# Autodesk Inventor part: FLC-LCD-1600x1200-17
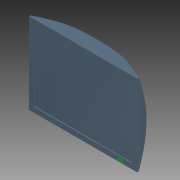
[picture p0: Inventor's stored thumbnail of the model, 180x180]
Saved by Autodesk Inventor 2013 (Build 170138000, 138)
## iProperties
Created: 2004-11
Part Number: FLC-LCD-1600x1200-17
Document SubType Name: Modeling
Designer: Autodesk, Inc.
Manufacturer: Standard
Standards Organization: Custom
Description: LCD MONITOR, 1600x1200, TOUCH
Mass: 4499.96 g
Surface Area: 2808.96 cm^2
Volume: 4499.96 cm^3
Density: 1 g/cm^3
Material: Allgemein
CAGE: 1LJX3
Dept. ID: Product Design
Description #2: ---
Finish #1: ---
Finish #2: ---
Material ID: ---
Project Number: ---
Author: Autodesk, Inc.
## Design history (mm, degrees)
sketch "Sketch1"
  geometry: L1 (-193.04, 144.78)-(193.04, 144.78); L2 (193.04, 144.78)-(193.04, -144.78); L3 (193.04, -144.78)-(-193.04, -144.78); L4 (-193.04, -144.78)-(-193.04, 144.78); L5 (-193.04, 144.78)-(193.04, -144.78); 3 further points
  constraints: 10 end point, 2 midpoint, 2 parallel, 1 horizontal, 1 horizontal alignment, 1 perpendicular, 1 vertical alignment
  dimensions: "d0" = 482.6 distance of L1.start L2.end; "d1" = 36.8699 deg angle of L3 L5
extrude "Extrusion1" new body sketch "Sketch1" stored distance "d2" = 50.8; taper "d3" = 0 deg
sketch "Sketch2"
  geometry: L1 (193.04, 144.78)-(193.04, -144.78) reference; L2 (-193.04, 144.78)-(193.04, 144.78) reference; L3 (-193.04, -144.78)-(-193.04, 144.78) reference; L4 (193.04, -144.78)-(-193.04, -144.78) reference; L5 (174.875, 126.615)-(174.875, -126.615); L6 (174.875, -126.615)-(-174.875, -126.615); L7 (-174.875, -126.615)-(-174.875, 126.615); L8 (-174.875, 126.615)-(174.875, 126.615); L9 (-174.875, 126.615)-(174.875, -126.615)
  constraints: 10 end point, 3 other
  dimensions: "d4" = 431.8 distance of L7.end L5.end
extrude "Extrusion2" cut sketch "Sketch2" distance "d5" = 3.175; taper "d6" = 0 deg
sketch "Sketch3"
  geometry: L1 (126.154, -132.337)-(139.952, -132.337); L2 (139.952, -132.337)-(139.952, -140.907); L3 (139.952, -140.907)-(126.154, -140.907); L4 (126.154, -140.907)-(126.154, -132.337); 2 further points
  constraints: 8 end point, 2 midpoint, 2 parallel, 2 vertical alignment, 1 horizontal, 1 perpendicular, 4 other
extrude "Extrusion3" join sketch "Sketch3" distance "d7" = 0.254; taper "d8" = 0 deg
sketch "Sketch4"
  geometry: L1 (193.04, -25.4)-(-193.04, -25.4) reference; L2 (193.04, 25.4)-(193.04, -25.4) reference; L3 (0, -57.634)-(0, 137.811) reference; L4 (0, -25.4)-(126.407, -25.4); A1 r 135.29 centre (126.407, 109.89) between (126.407, -25.4) and (193.04, -7.853)
  constraints: 3 point on line, 2 end point, 2 point on circle, 1 centre point, 1 midpoint, 1 tangent
revolve "Revolution1" sketch "Sketch4" stored, may be unused: angle "d10" = 90 deg
sketch "Sketch5"
  geometry: L1 (371.121, 0)-(0, 0) reference; L2 (66.633, -50.8)-(319.447, -50.8) reference; L3 (83.961, -50.8)-(287.161, -50.8); L4 (287.161, -50.8)-(287.161, -15.875); L5 (287.161, -15.875)-(83.961, -15.875); L6 (83.961, -15.875)-(83.961, -50.8); 2 further points
  constraints: 8 end point, 2 midpoint, 2 parallel, 1 horizontal, 1 perpendicular, 1 point on line, 1 vertical alignment
  dimensions: "d12" = 34.925 distance of L3.end L4.end; "d13" = 203.2 distance between parallel lines of L4 L6
extrude "Extrusion4" cut sketch "Sketch5" distance "d14" = 47.625; taper "d15" = 0 deg
sketch "Sketch6"
  geometry: 2 further points
  dimensions: "d16" = 50 horizontal distance of point (0, 0) point (-50, -50); "d17" = 50 horizontal distance of point (0, 0) point (-50, -50) (= d16)
hole "Hole1" sketch "Sketch6" diameter "d18" = 4.1402; stored, may be unused: countersink angle "d22" = 82 deg, drill point angle "d24" = 118 deg; dims "d19" = 12.7, "d20" = 9.525, "d21" = 6.35, "d23" = 12.7
pattern_linear "Rectangular Pattern1" dims "d27" = 100 (= 2 x d16)
sketch "Sketch9"
  geometry: L1 (83.961, -15.875)-(287.161, -15.875) reference; L2 (267.881, -41.95)-(249.291, -41.95); L3 (244.591, -37.25)-(244.591, -26.25); L4 (249.291, -21.55)-(267.881, -21.55); L5 (272.581, -26.25)-(272.581, -37.25); L6 (272.581, -31.75)-(244.591, -31.75); L7 (258.586, -41.95)-(258.586, -21.55); L8 (246.471, -37.25)-(246.471, -26.25); L9 (249.291, -23.43)-(267.881, -23.43); L10 (270.701, -26.25)-(270.701, -37.25); L11 (267.881, -40.07)-(249.291, -40.07); L12 (270.701, -28.535)-(265.596, -23.43); L13 (246.471, -28.535)-(251.576, -23.43); L14 (287.161, -15.875)-(287.161, -42.639) reference; A1 r 4.7 centre (267.881, -37.25) between (267.881, -41.95) and (272.581, -37.25); A2 r 4.7 centre (249.291, -37.25) between (244.591, -37.25) and (249.291, -41.95); A3 r 4.7 centre (249.291, -26.25) between (249.291, -21.55) and (244.591, -26.25); A4 r 4.7 centre (267.881, -26.25) between (272.581, -26.25) and (267.881, -21.55); A5 r 2.82 centre (249.291, -37.25) between (246.471, -37.25) and (249.291, -40.07); A6 r 2.82 centre (249.291, -26.25) between (249.291, -23.43) and (246.471, -26.25); A7 r 2.82 centre (267.881, -26.25) between (270.701, -26.25) and (267.881, -23.43); A8 r 2.82 centre (267.881, -37.25) between (267.881, -40.07) and (270.701, -37.25)
  constraints: 24 end point, 16 point on circle, 8 centre point, 8 tangent, 4 midpoint, 4 parallel, 4 point on line, 3 equal radius, 3 perpendicular, 1 horizontal, 8 other
  dimensions: "d74" = 4.7 radius of A1; "d75" = 20.4 distance between parallel lines of L4 L2; "d76" = 27.99 distance between parallel lines of L3 L5; "d77" = 24.23 distance between parallel lines of L8 L10; "d79" = 7.01 distance from line of L7 L12.end; "d80" = 28.575 distance between parallel lines of L14 L7; "d81" = 15.875 distance between parallel lines of L1 L6
extrude "Extrusion5" cut sketch "Sketch9" distance "d55" = 16.69; taper "d56" = 0 deg
extrude "Extrusion6" cut sketch "Sketch9" distance "d82" = 1.6002; taper "d83" = 0 deg
extrude "Extrusion7" join sketch "Sketch9" distance "d84" = 1; taper "d85" = 0 deg
sketch "Sketch10"
  geometry: L1 (258.586, -41.95)-(258.586, -21.55) reference; L2 (272.581, -31.75)-(244.591, -31.75) reference; L3 (258.086, -28.24)-(259.086, -28.24); L4 (259.086, -28.24)-(259.086, -31.24); L5 (259.086, -31.24)-(258.086, -31.24); L6 (258.086, -31.24)-(258.086, -28.24); L7 (251.076, -32.23)-(252.076, -32.23); L8 (252.076, -32.23)-(252.076, -35.23); L9 (252.076, -35.23)-(251.076, -35.23); L10 (251.076, -35.23)-(251.076, -32.23); L11 (265.096, -32.23)-(266.096, -32.23); L12 (266.096, -32.23)-(266.096, -35.23); L13 (266.096, -35.23)-(265.096, -35.23); L14 (265.096, -35.23)-(265.096, -32.23); 3 further points
  constraints: 24 end point, 6 parallel, 3 equal length, 3 horizontal, 3 midpoint, 3 perpendicular, 4 other
  dimensions: "d86" = 1 distance of L3.start L3.end; "d87" = 3 distance of L5.end L3.start; "d88" = 2.01 distance from line of L2 point (259.086, -29.74); "d89" = 1.98 distance from line of L2 point (266.096, -33.73); "d90" = 7.01 distance from line of L1 point (265.596, -32.23)
extrude "Extrusion8" join sketch "Sketch10" distance "d91" = 9.525; taper "d92" = 0 deg
sketch "Sketch14"
  geometry: L1 (134.076, -30.75)-(134.076, -34.34); L2 (132.806, -35.61)-(111.316, -35.61); L3 (110.046, -34.34)-(110.046, -30.75); L4 (110.046, -30.75)-(110.449, -29.246); L5 (112.216, -27.89)-(131.905, -27.89); L6 (133.673, -29.246)-(134.076, -30.75); L7 (122.061, -35.61)-(122.061, -27.89); L8 (83.961, -15.875)-(287.161, -15.875) reference; L9 (83.961, -39.176)-(83.961, -15.875) reference; L10 (111.316, -35)-(132.806, -35); L11 (133.466, -34.34)-(133.466, -30.83); L12 (133.466, -30.83)-(133.084, -29.404); L13 (131.905, -28.5)-(112.216, -28.5); L14 (111.038, -29.404)-(110.656, -30.83); L15 (110.656, -30.83)-(110.656, -34.34); L16 (134.076, -31.75)-(110.046, -31.75); L17 (132.361, -30.59)-(130.861, -30.59); L18 (130.861, -30.59)-(130.861, -29.09); L19 (130.861, -29.09)-(132.361, -29.09); L20 (132.361, -29.09)-(132.361, -30.59); L21 (130.451, -30.59)-(128.951, -30.59); L22 (128.951, -30.59)-(128.951, -29.09); L23 (128.951, -29.09)-(130.451, -29.09); L24 (130.451, -29.09)-(130.451, -30.59); L25 (128.541, -30.59)-(127.041, -30.59); L26 (127.041, -30.59)-(127.041, -29.09); L27 (127.041, -29.09)-(128.541, -29.09); L28 (128.541, -29.09)-(128.541, -30.59); L29 (126.631, -30.59)-(125.131, -30.59); L30 (125.131, -30.59)-(125.131, -29.09); L31 (125.131, -29.09)-(126.631, -29.09); L32 (126.631, -29.09)-(126.631, -30.59); L33 (124.721, -30.59)-(123.221, -30.59); L34 (123.221, -30.59)-(123.221, -29.09); L35 (123.221, -29.09)-(124.721, -29.09); L36 (124.721, -29.09)-(124.721, -30.59); L37 (122.811, -30.59)-(121.311, -30.59); L38 (121.311, -30.59)-(121.311, -29.09); L39 (121.311, -29.09)-(122.811, -29.09); L40 (122.811, -29.09)-(122.811, -30.59); L41 (120.901, -30.59)-(119.401, -30.59); L42 (119.401, -30.59)-(119.401, -29.09); L43 (119.401, -29.09)-(120.901, -29.09); L44 (120.901, -29.09)-(120.901, -30.59); L45 (118.991, -30.59)-(117.491, -30.59); L46 (117.491, -30.59)-(117.491, -29.09); L47 (117.491, -29.09)-(118.991, -29.09); L48 (118.991, -29.09)-(118.991, -30.59); L49 (132.361, -32.5)-(130.861, -32.5); L50 (130.861, -32.5)-(130.861, -31); L51 (130.861, -31)-(132.361, -31); L52 (132.361, -31)-(132.361, -32.5); L53 (130.451, -32.5)-(128.951, -32.5); L54 (128.951, -32.5)-(128.951, -31); L55 (128.951, -31)-(130.451, -31); L56 (130.451, -31)-(130.451, -32.5); L57 (128.541, -32.5)-(127.041, -32.5); L58 (127.041, -32.5)-(127.041, -31); L59 (127.041, -31)-(128.541, -31); L60 (128.541, -31)-(128.541, -32.5); L61 (126.631, -32.5)-(125.131, -32.5); L62 (125.131, -32.5)-(125.131, -31); L63 (125.131, -31)-(126.631, -31); L64 (126.631, -31)-(126.631, -32.5)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; A1 r 1.27 centre (132.806, -34.34) between (132.806, -35.61) and (134.076, -34.34); A2 r 1.27 centre (111.316, -34.34) between (110.046, -34.34) and (111.316, -35.61); A3 r 1.83 centre (112.216, -29.72) between (112.216, -27.89) and (110.449, -29.246); A4 r 1.83 centre (131.905, -29.72) between (133.673, -29.246) and (131.905, -27.89); A5 r 0.66 centre (132.806, -34.34) between (132.806, -35) and (133.466, -34.34); A6 r 1.22 centre (131.905, -29.72) between (133.084, -29.404) and (131.905, -28.5); A7 r 1.22 centre (112.216, -29.72) between (112.216, -28.5) and (111.038, -29.404); A8 r 0.66 centre (111.316, -34.34) between (110.656, -34.34) and (111.316, -35); 7 further points
  constraints: 270 end point, 16 point on circle, 13 symmetric about line, 12 parallel, 12 perpendicular, 10 midpoint, 8 centre point, 8 tangent, 5 horizontal, 4 point on line, 2 vertical, 1 horizontal alignment, 1 vertical alignment, 197 other
  dimensions: "d100" = 24.03 distance between parallel lines of L3 L1; "d101" = 1.27 radius of A2; "d102" = 1.83 radius of A3; "d103" = 105 deg angle of L6 L5; "d104" = 7.72 distance between parallel lines of L5 L2; "d105" = 3.59 distance of L3.start L3.end; "d106" = 15.875 distance from line of L8 point (122.061, -31.75); "d107" = 38.1 distance between parallel lines of L9 L7; "d108" = 6.5 distance between parallel lines of L13 L10; "d110" = 1.5 distance of L18.end L19.end; "d111" = 10.3 distance between parallel lines of L7 L20; "d112" = 2.66 distance between parallel lines of L16 L19; "d115" = 1.91 distance of L17.start L21.start; "d118" = 1.91 distance of L17.start L49.start; "d121" = 0.5 distance of L119.end L117.start; "d122" = 0.25 distance between parallel lines of L16 L119 (= 0.5 x d121); "d123" = 4.2 distance of L113.end L114.end; "d124" = 8.69 distance between parallel lines of L116 L7; "d125" = 1.25 distance of L122.end L123.end; "d126" = 0.4 distance between parallel lines of L116 L122; "d127" = 0.4 distance between parallel lines of L119 L121; "d134" = 32.51 distance of point (138.316, -31.75) point (105.806, -31.75)
extrude "Extrusion9" cut sketch "Sketch14" distance "d128" = 6.5; taper "d129" = 0 deg
extrude "Extrusion10" cut sketch "Sketch14" distance "d130" = 7.5; taper "d131" = 0 deg
extrude "Extrusion11" join sketch "Sketch14" distance "d132" = 0.25; taper "d133" = 0 deg
hole "Hole3" sketch "Sketch14" diameter "d135" = 2.159; stored, may be unused: countersink angle "d139" = 82 deg, drill point angle "d141" = 118 deg; dims "d136" = 12.7, "d137" = 9.525, "d138" = 6.35, "d140" = 9.525
sketch "Sketch15"
  geometry: L1 (168.353, -32.872)-(167.806, -29.773); L2 (165.38, -27.737)-(154.941, -27.737); L3 (152.515, -29.773)-(151.968, -32.872); L4 (154.395, -35.763)-(165.926, -35.763); L5 (160.161, -35.763)-(160.161, -27.737); L6 (83.961, -15.875)-(287.161, -15.875) reference; L7 (83.961, -39.176)-(83.961, -15.875) reference; L8 (165.926, -35.509)-(154.395, -35.509); L9 (152.219, -32.916)-(152.765, -29.817); L10 (154.941, -27.991)-(165.38, -27.991); L11 (167.556, -29.817)-(168.103, -32.916); L12 (168.155, -31.75)-(152.166, -31.75); L13 (165.647, -33.172)-(164.275, -30.328); C1 r 0.635 at (165.647, -33.172); C2 r 0.635 at (162.904, -33.172); C3 r 0.635 at (160.161, -33.172); C4 r 0.635 at (157.417, -33.172); C5 r 0.635 at (154.674, -33.172); C6 r 0.635 at (164.275, -30.328); C7 r 0.635 at (161.532, -30.328); C8 r 0.635 at (158.789, -30.328); C9 r 0.635 at (156.046, -30.328); C10 r 0.635 at (153.303, -30.328); C11 r 1.905 at (147.727, -31.75); C12 r 1.905 at (172.594, -31.75); A1 r 2.464 centre (165.38, -30.201) between (167.806, -29.773) and (165.38, -27.737); A2 r 2.464 centre (154.941, -30.201) between (154.941, -27.737) and (152.515, -29.773); A3 r 2.464 centre (154.395, -33.299) between (151.968, -32.872) and (154.395, -35.763); A4 r 2.464 centre (165.926, -33.299) between (165.926, -35.763) and (168.353, -32.872); A5 r 2.21 centre (154.395, -33.299) between (152.219, -32.916) and (154.395, -35.509); A6 r 2.21 centre (154.941, -30.201) between (154.941, -27.991) and (152.765, -29.817); A7 r 2.21 centre (165.38, -30.201) between (167.556, -29.817) and (165.38, -27.991); A8 r 2.21 centre (165.926, -33.299) between (165.926, -35.509) and (168.103, -32.916); 1 further point
  constraints: 22 end point, 20 centre point, 16 point on circle, 7 tangent, 4 midpoint, 4 point on line, 3 parallel, 2 horizontal, 1 equal radius, 1 perpendicular, 30 other
  dimensions: "d142" = 16.4592 dimension on A3 A4; "d143" = 2.4638 radius of A3; "d144" = 10 deg angle of L5 L1; "d145" = 8.0264 distance between parallel lines of L2 L4; "d147" = 76.2 distance between parallel lines of L7 L5; "d148" = 0.254 distance between parallel lines of L4 L8; "d149" = 15.875 distance between parallel lines of L6 L12; "d150" = 1.27 diameter of C1; "d151" = 1.4224 distance from line of L12 L13.start; "d152" = 5.4864 distance from line of L13.start L5; "d153" = 1.4224 distance from line of L13.end L12 (= d151); "d154" = 4.1148 distance from line of L13.end L5; "d155" = 3.15819 distance of L13.start L13.end (derived); "d158" = 2.7432 distance of L13.start C2.centre; "d161" = 3.15819 distance of L13.start C6.centre (= d155); "d166" = 3.81 diameter of C11; "d174" = 24.8666 distance of C12.centre C11.centre
extrude "Extrusion12" join sketch "Sketch15" distance "d164" = 6.0452; taper "d165" = 0 deg
sketch "Sketch16"
  geometry: C1 r 1.905 at (0, 0) reference; C2 r 1.905 at (24.867, 0) reference
hole "Hole4" sketch "Sketch16" diameter "d167" = 2.159; stored, may be unused: countersink angle "d171" = 82 deg, drill point angle "d173" = 118 deg; dims "d168" = 12.7, "d169" = 9.525, "d170" = 6.35, "d172" = 6.35
sketch "Sketch17"
  geometry: L1 (202.486, -27.86)-(202.486, -34.01); L2 (202.486, -34.01)-(200.856, -35.64); L3 (200.856, -35.64)-(195.666, -35.64); L4 (195.666, -35.64)-(194.036, -34.01); L5 (194.036, -34.01)-(194.036, -27.86); L6 (194.036, -27.86)-(202.486, -27.86); L7 (198.261, -35.64)-(198.261, -27.86); L8 (83.961, -15.875)-(287.161, -15.875) reference; L9 (83.961, -39.176)-(83.961, -15.875) reference; L10 (201.061, -33.34)-(195.461, -33.34); L11 (195.461, -33.34)-(195.461, -30.16); L12 (195.461, -30.16)-(201.061, -30.16); L13 (201.061, -30.16)-(201.061, -33.34); 3 further points
  constraints: 22 end point, 5 midpoint, 4 parallel, 4 perpendicular, 1 horizontal, 1 horizontal alignment, 1 vertical, 1 vertical alignment, 1 other
  dimensions: "d175" = 8.45 distance between parallel lines of L5 L1; "d176" = 7.78 distance between parallel lines of L6 L3; "d177" = 1.63 horizontal distance of L3.end L4.end; "d178" = 15.875 distance from line of point (198.261, -31.75) L8; "d179" = 114.3 distance between parallel lines of L9 L7; "d180" = 3.18 distance of L12.end L10.start; "d181" = 5.6 distance of L10.start L10.end
extrude "USB BPort" cut sketch "Sketch17" distance "d182" = 6.35; taper "d183" = 0 deg
sketch "Sketch18"
  geometry: L1 (-168.818, 126.615)-(168.818, 126.615); L2 (168.818, 126.615)-(168.818, -126.615); L3 (168.818, -126.615)-(-168.818, -126.615); L4 (-168.818, -126.615)-(-168.818, 126.615); L5 (174.875, 126.615)-(-174.875, 126.615) reference; L6 (-174.875, 126.615)-(-174.875, -126.615) reference; L7 (-174.875, -126.615)-(174.875, -126.615) reference; L8 (174.875, -126.615)-(174.875, 126.615) reference; L9 (-174.875, 126.615)-(174.875, 126.615) reference; L10 (174.875, -126.615)-(-174.875, -126.615) reference; 3 further points; 1 other entity
  constraints: 2 collinear, 2 midpoint, 1 coincident, 2 other
feature "Decal2" sketch "Sketch18"
body "Solid1"
node "Projected Loop1"
node "Image3"
other parameters: "d9" = 90 deg
